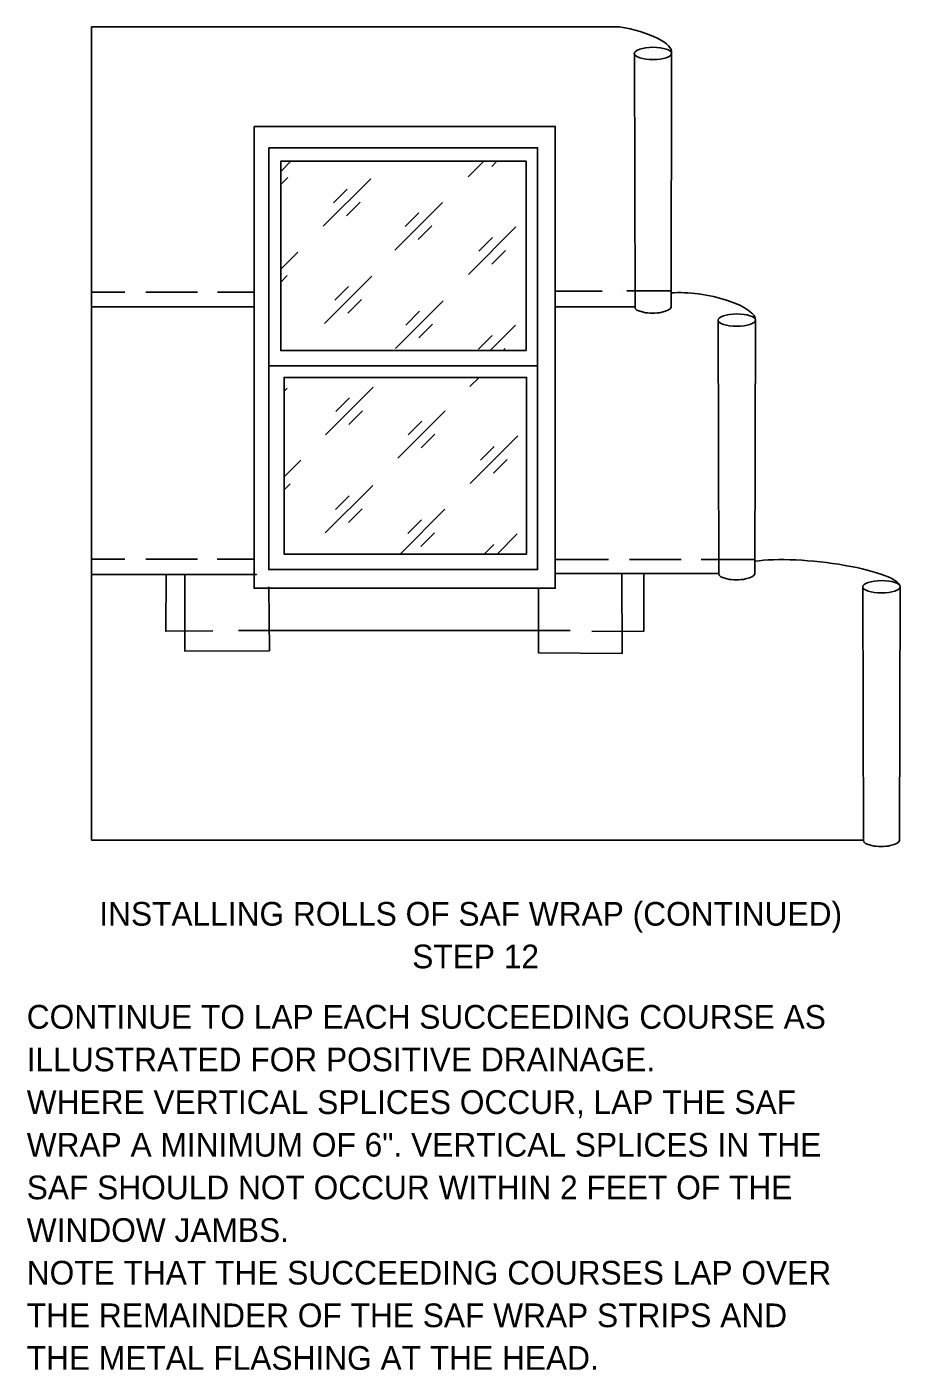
# Model space of a CAD drawing. Extents: x 1.135 to 1.319, y -0.622 to -0.338.
import ezdxf

# ---------------------------------------------------------------- set-up
doc = ezdxf.new("R2010")
doc.units = 0
for name, color, linetype in [('Default', 7, 'Continuous'), ('Sheets_General Details', 7, 'Continuous'), ('Sheets_General Details - Sheet Standard Text', 7, 'Continuous')]:
    doc.layers.add(name, color=color, linetype=linetype)

msp = doc.modelspace()

# ---------------------------------------------------------------- linework, layer by layer
at = {"layer": 'Default'}
msp.add_line((1.18297, -0.45362), (1.18297, -0.45366), dxfattribs=at)
at = {"layer": 'Sheets_General Details - Sheet Standard Text'}
for p, q in [((1.14814, -0.50975), (1.14814, -0.33809)), ((1.14814, -0.33809), (1.25962, -0.33809)), ((1.26287, -0.3972), (1.26273, -0.34371)), ((1.27047, -0.3972), (1.27058, -0.34381)), ((1.1881, -0.36861), (1.19024, -0.36647)), ((1.22769, -0.36977), (1.23098, -0.36647)), ((1.23262, -0.36757), (1.23372, -0.36647)), ((1.1881, -0.37134), (1.18959, -0.36986)), ((1.19707, -0.38018), (1.2071, -0.37015)), ((1.19926, -0.37525), (1.20215, -0.37236)), ((1.202, -0.37799), (1.20489, -0.3751)), ((1.21218, -0.38519), (1.22221, -0.37515)), ((1.21437, -0.38026), (1.21726, -0.37737)), ((1.21711, -0.38299), (1.22, -0.38011)), ((1.2277, -0.39035), (1.23774, -0.38031)), ((1.2299, -0.38542), (1.23278, -0.38253)), ((1.23263, -0.38816), (1.23552, -0.38527)), ((1.1881, -0.38921), (1.19168, -0.38563)), ((1.1881, -0.39195), (1.18947, -0.39058)), ((1.19733, -0.40072), (1.20736, -0.39069)), ((1.14814, -0.39407), (1.15521, -0.39407)), ((1.15962, -0.39407), (1.15962, -0.39407)), ((1.15962, -0.39407), (1.17053, -0.39407)), ((1.17053, -0.39407), (1.17053, -0.39407)), ((1.17473, -0.39407), (1.17473, -0.39407)), ((1.17473, -0.39407), (1.18248, -0.39407)), ((1.19952, -0.39579), (1.20241, -0.3929)), ((1.24602, -0.39386), (1.25597, -0.39386)), ((1.25597, -0.39386), (1.25597, -0.39386)), ((1.26017, -0.39386), (1.26017, -0.39386)), ((1.26115, -0.39383), (1.27048, -0.39383)), ((1.20226, -0.39853), (1.20515, -0.39564)), ((1.21234, -0.40595), (1.22237, -0.39592)), ((1.14814, -0.39717), (1.18248, -0.39717)), ((1.21453, -0.40102), (1.21742, -0.39813)), ((1.24602, -0.39717), (1.26285, -0.39717)), ((1.21727, -0.40376), (1.22015, -0.40087)), ((1.23232, -0.4064), (1.23767, -0.40104)), ((1.28056, -0.45348), (1.28042, -0.39999)), ((1.28816, -0.45348), (1.28827, -0.40009)), ((1.22983, -0.40614), (1.23272, -0.40325)), ((1.23506, -0.4064), (1.23546, -0.40599)), ((1.22803, -0.41401), (1.22995, -0.41209)), ((1.18881, -0.41501), (1.18948, -0.41434)), ((1.19756, -0.42419), (1.20759, -0.41415)), ((1.19975, -0.41926), (1.20264, -0.41637)), ((1.20249, -0.42199), (1.20538, -0.41911)), ((1.21279, -0.42914), (1.22283, -0.41911)), ((1.21498, -0.42421), (1.21787, -0.42133)), ((1.21772, -0.42695), (1.22061, -0.42406)), ((1.22808, -0.43446), (1.23811, -0.42443)), ((1.23027, -0.42953), (1.23316, -0.42664)), ((1.18881, -0.43307), (1.19232, -0.42956)), ((1.233, -0.43227), (1.23589, -0.42938)), ((1.18881, -0.43581), (1.19011, -0.43452)), ((1.19748, -0.4449), (1.20751, -0.43487)), ((1.19967, -0.43998), (1.20256, -0.43709)), ((1.20241, -0.44271), (1.2053, -0.43982)), ((1.21329, -0.44937), (1.22274, -0.43992)), ((1.2149, -0.44503), (1.21779, -0.44214)), ((1.21764, -0.44776), (1.22053, -0.44488)), ((1.23101, -0.44937), (1.23306, -0.44732)), ((1.23375, -0.44937), (1.23801, -0.44511)), ((1.14814, -0.45042), (1.15519, -0.45042)), ((1.1596, -0.45042), (1.1596, -0.45042)), ((1.1596, -0.45042), (1.17051, -0.45042)), ((1.17051, -0.45042), (1.17051, -0.45042)), ((1.17471, -0.45042), (1.17471, -0.45042)), ((1.17471, -0.45042), (1.18248, -0.45042)), ((1.24602, -0.45048), (1.2573, -0.45048)), ((1.26171, -0.45048), (1.26171, -0.45048)), ((1.26171, -0.45048), (1.27261, -0.45048)), ((1.27261, -0.45048), (1.27261, -0.45048)), ((1.27681, -0.45048), (1.27681, -0.45048)), ((1.27681, -0.45048), (1.28817, -0.45048)), ((1.24602, -0.45348), (1.28056, -0.45348)), ((1.18297, -0.45366), (1.14814, -0.45366)), ((1.3111, -0.50975), (1.31095, -0.45627)), ((1.31869, -0.50975), (1.31881, -0.45637)), ((1.17916, -0.46549), (1.24915, -0.46551)), ((1.31107, -0.50975), (1.14814, -0.50975)), ((1.14814, -0.50975), (1.14814, -0.50975))]:
    msp.add_line(p, q, dxfattribs=at)
for points in [[(1.18248, -0.35911), (1.24602, -0.35911), (1.24602, -0.45657), (1.18248, -0.45657)], [(1.18556, -0.36362), (1.24232, -0.36362), (1.24232, -0.40965), (1.18556, -0.40965)], [(1.23989, -0.4064), (1.1881, -0.4064), (1.1881, -0.36647), (1.23989, -0.36647)], [(1.18556, -0.40965), (1.24232, -0.40965), (1.24232, -0.45263), (1.18556, -0.45263)], [(1.23999, -0.44937), (1.18881, -0.44937), (1.18881, -0.41209), (1.23999, -0.41209)]]:
    msp.add_lwpolyline(points, close=True, dxfattribs=at)
for points in [[(1.24252, -0.45657), (1.24249, -0.47018), (1.26015, -0.47035), (1.26012, -0.45348)], [(1.26474, -0.45348), (1.26471, -0.46565), (1.25378, -0.46569)], [(1.16394, -0.45366), (1.16382, -0.46566), (1.1738, -0.46553)], [(1.16783, -0.45366), (1.16788, -0.46987), (1.18572, -0.46978), (1.18562, -0.45625)]]:
    msp.add_lwpolyline(points, dxfattribs=at)
for centre, major_axis, ratio, start_param, end_param in [((1.25946, -0.34164), (0.01112, -0.00194), 0.311991, 0, 1.611099), ((1.27715, -0.39816), (0.01112, -0.00194), 0.311991, 0, 2.268179), ((1.26666, -0.39723), (-0.00381, -0.00004), 0.337863, 6.224642, 9.424778), ((1.30163, -0.45449), (-0.01718, 0.00188), 0.202486, 3.175797, 5.635345), ((1.28435, -0.45351), (-0.00381, -0.00004), 0.337863, 6.224642, 9.424778), ((1.31488, -0.50979), (-0.00381, -0.00004), 0.337863, 6.224642, 9.424778)]:
    msp.add_ellipse(centre, major_axis=major_axis, ratio=ratio, start_param=start_param, end_param=end_param, dxfattribs=at)
for centre in [(1.26666, -0.3437), (1.28435, -0.39998), (1.31489, -0.45626)]:
    msp.add_ellipse(centre, major_axis=(-0.00394, -0.00001), ratio=0.327242, dxfattribs=at)

# ---------------------------------------------------------------- texts
at = {"layer": 'Sheets_General Details'}
for s, p in [('INSTALLING ROLLS OF SAF WRAP (CONTINUED)', (1.1498, -0.52779)), ('STEP 12', (1.21585, -0.53679)), ('CONTINUE TO LAP EACH SUCCEEDING COURSE AS', (1.13449, -0.54953)), ('ILLUSTRATED FOR POSITIVE DRAINAGE.', (1.13449, -0.55853)), ('WHERE VERTICAL SPLICES OCCUR, LAP THE SAF', (1.13449, -0.56753)), ('WRAP A MINIMUM OF 6". VERTICAL SPLICES IN THE', (1.13449, -0.57653)), ('SAF SHOULD NOT OCCUR WITHIN 2 FEET OF THE', (1.13449, -0.58553)), ('WINDOW JAMBS.', (1.13449, -0.59453)), ('NOTE THAT THE SUCCEEDING COURSES LAP OVER', (1.13449, -0.60353)), ('THE REMAINDER OF THE SAF WRAP STRIPS AND', (1.13449, -0.61253)), ('THE METAL FLASHING AT THE HEAD.', (1.13449, -0.62153))]:
    msp.add_text(s, height=0.005, dxfattribs=at).set_placement(p)

doc.saveas('drawing.dxf')
